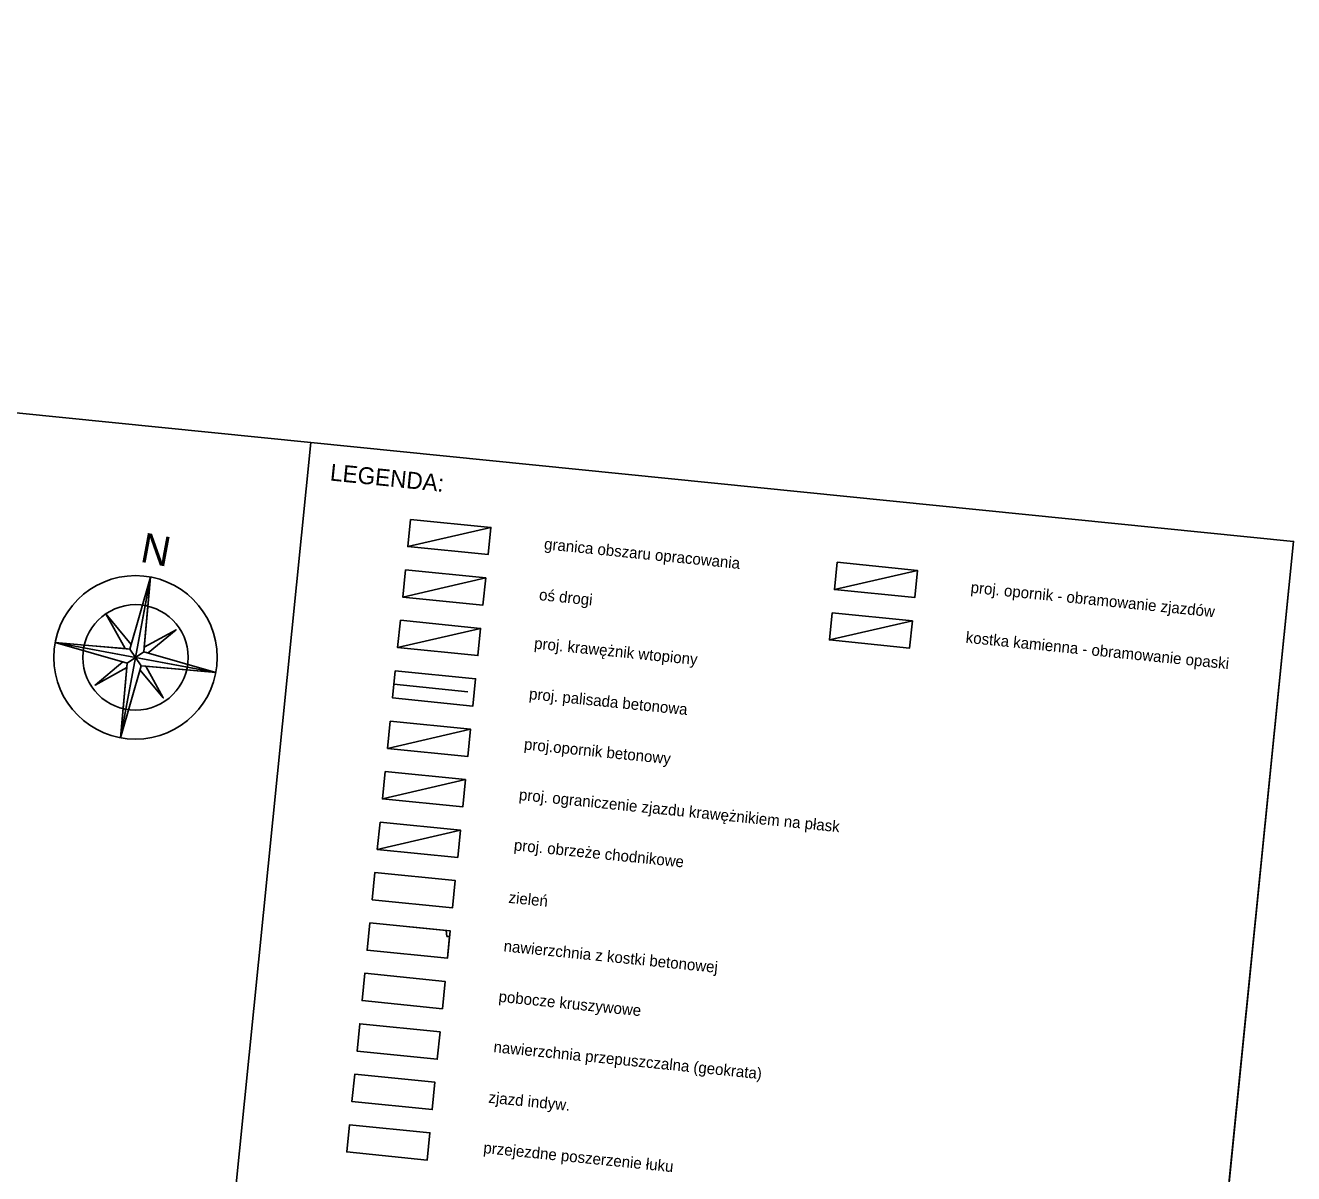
# Model space of a CAD drawing. Extents: x 7481518 to 7481979, y 5775984 to 5776168.
# Drawn here: x 7481859.8 to 7481962.5, y 5776073.9 to 5776166.9 of the extents above; entities that cross this region are included whole.
import ezdxf

# ---------------------------------------------------------------- set-up
doc = ezdxf.new("R2010")
doc.units = 0
for name, color, linetype in [('kraweznik', 7, 'Continuous'), ('numer', 7, 'Continuous'), ('odwierty', 7, 'Continuous'), ('opis', 7, 'Continuous'), ('pomoc', 7, 'Continuous'), ('proj_linia_rozgraniczajaca_kanalizacja', 7, 'Continuous'), ('sciek podchodnikowy', 7, 'Continuous')]:
    doc.layers.add(name, color=color, linetype=linetype)

msp = doc.modelspace()

# ---------------------------------------------------------------- linework, layer by layer
at = {"layer": 'kraweznik'}
for p, q in [((7481893.92, 5776093.06), (7481893.88, 5776093.55)), ((7481894.16, 5776093.08), (7481893.92, 5776093.06))]:
    msp.add_line(p, q, dxfattribs=at)
for points in [[(7481893.88, 5776093.55), (7481887.7, 5776094.17), (7481887.48, 5776091.96), (7481893.98, 5776091.31), (7481894.02, 5776091.65), (7481894.16, 5776093.08)], [(7481887.07, 5776087.88), (7481893.57, 5776087.22), (7481893.79, 5776089.43), (7481887.29, 5776090.09), (7481887.07, 5776087.88)], [(7481886.66, 5776083.79), (7481893.16, 5776083.13), (7481893.38, 5776085.35), (7481886.88, 5776086), (7481886.66, 5776083.79)], [(7481886.24, 5776079.7), (7481892.75, 5776079.05), (7481892.97, 5776081.26), (7481886.47, 5776081.91), (7481886.24, 5776079.7)], [(7481885.83, 5776075.62), (7481892.34, 5776074.96), (7481892.56, 5776077.17), (7481886.06, 5776077.83), (7481885.83, 5776075.62)]]:
    msp.add_lwpolyline(points, dxfattribs=at)
at = {"layer": 'numer'}
for p, q in [((7481889.95, 5776116.48), (7481896.67, 5776118.03)), ((7481888.71, 5776104.22), (7481895.44, 5776105.78))]:
    msp.add_line(p, q, dxfattribs=at)
at = {"layer": 'odwierty'}
msp.add_lwpolyline([(7481887.89, 5776096.05), (7481894.39, 5776095.39), (7481894.62, 5776097.6), (7481888.11, 5776098.26), (7481887.89, 5776096.05)], dxfattribs=at)
at = {"layer": 'opis'}
msp.add_line((7481895.03, 5776101.69), (7481888.3, 5776100.13), dxfattribs=at)
at = {"layer": 'pomoc'}
for p, q in [((7481890.77, 5776124.65), (7481897.5, 5776126.21)), ((7481962.51, 5776125.07), (7481948.28, 5775983.78)), ((7481869.94, 5776122.19), (7481867.51, 5776109.17)), ((7481869.94, 5776122.19), (7481868.26, 5776116.35)), ((7481869.94, 5776122.19), (7481869.4, 5776116.14)), ((7481890.36, 5776120.57), (7481893.72, 5776121.34)), ((7481893.72, 5776121.34), (7481897.09, 5776122.12)), ((7481866.31, 5776119.2), (7481867.89, 5776116.39)), ((7481866.31, 5776119.2), (7481868.36, 5776116.71)), ((7481872, 5776117.92), (7481869.43, 5776116.5)), ((7481872, 5776117.92), (7481869.75, 5776116.04)), ((7481862.22, 5776116.89), (7481875.23, 5776114.46)), ((7481862.22, 5776116.89), (7481868.05, 5776115.21)), ((7481862.22, 5776116.89), (7481868.26, 5776116.35)), ((7481868.26, 5776116.35), (7481868.72, 5776115.68)), ((7481869.4, 5776116.14), (7481868.72, 5776115.68)), ((7481875.23, 5776114.46), (7481869.4, 5776116.14)), ((7481865.45, 5776113.43), (7481867.7, 5776115.32)), ((7481867.51, 5776109.17), (7481868.05, 5776115.21)), ((7481867.51, 5776109.17), (7481869.19, 5776115)), ((7481868.05, 5776115.21), (7481868.72, 5776115.68)), ((7481869.19, 5776115), (7481868.72, 5776115.68)), ((7481875.23, 5776114.46), (7481869.19, 5776115)), ((7481865.45, 5776113.43), (7481868.01, 5776114.85)), ((7481870.97, 5776112.4), (7481869.09, 5776114.65)), ((7481870.97, 5776112.4), (7481869.55, 5776114.97))]:
    msp.add_line(p, q, dxfattribs=at)
for points in [[(7481882.91, 5776133.08), (7481547.45, 5776166.87), (7481533.22, 5776025.59), (7481868.68, 5775991.8)], [(7481868.68, 5775991.8), (7481948.28, 5775983.78), (7481962.51, 5776125.07), (7481882.91, 5776133.08)], [(7481890.99, 5776126.86), (7481897.5, 5776126.21), (7481897.27, 5776124), (7481890.77, 5776124.65)], [(7481925.54, 5776123.38), (7481932.04, 5776122.73), (7481931.82, 5776120.52), (7481925.32, 5776121.17)], [(7481890.58, 5776122.78), (7481897.09, 5776122.12), (7481896.86, 5776119.91), (7481890.36, 5776120.57)], [(7481925.13, 5776119.3), (7481931.63, 5776118.64), (7481931.41, 5776116.43), (7481924.91, 5776117.09)], [(7481890.17, 5776118.69), (7481896.67, 5776118.03), (7481896.45, 5776115.82), (7481889.95, 5776116.48)], [(7481889.76, 5776114.6), (7481896.26, 5776113.95), (7481896.04, 5776111.74), (7481889.54, 5776112.39)], [(7481889.35, 5776110.52), (7481895.85, 5776109.86), (7481895.63, 5776107.65), (7481889.13, 5776108.31)], [(7481888.94, 5776106.43), (7481895.44, 5776105.78), (7481895.22, 5776103.57), (7481888.71, 5776104.22)], [(7481888.53, 5776102.34), (7481895.03, 5776101.69), (7481894.81, 5776099.48), (7481888.3, 5776100.13)], [(7481888.11, 5776098.26), (7481894.62, 5776097.6), (7481894.39, 5776095.39), (7481887.89, 5776096.05)], [(7481887.7, 5776094.17), (7481894.21, 5776093.52), (7481893.98, 5776091.31), (7481887.48, 5776091.96)], [(7481887.29, 5776090.09), (7481893.79, 5776089.43), (7481893.57, 5776087.22), (7481887.07, 5776087.88)], [(7481886.88, 5776086), (7481893.38, 5776085.35), (7481893.16, 5776083.13), (7481886.66, 5776083.79)], [(7481886.47, 5776081.91), (7481892.97, 5776081.26), (7481892.75, 5776079.05), (7481886.24, 5776079.7)], [(7481886.06, 5776077.83), (7481892.56, 5776077.17), (7481892.34, 5776074.96), (7481885.83, 5776075.62)]]:
    msp.add_lwpolyline(points, close=True, dxfattribs=at)
for points in [[(7481869.73, 5776119.82), (7481869.94, 5776122.19), (7481869.51, 5776119.87)], [(7481867.89, 5776116.39), (7481868.26, 5776116.35), (7481868.36, 5776116.71), (7481866.31, 5776119.2), (7481867.89, 5776116.39)], [(7481869.51, 5776119.87), (7481868.72, 5776115.68), (7481869.4, 5776116.14), (7481869.43, 5776116.5), (7481869.73, 5776119.82)], [(7481869.43, 5776116.5), (7481869.4, 5776116.14), (7481869.75, 5776116.04), (7481872, 5776117.92), (7481869.43, 5776116.5)], [(7481864.58, 5776116.68), (7481862.22, 5776116.89), (7481864.53, 5776116.46)], [(7481864.53, 5776116.46), (7481868.72, 5776115.68), (7481868.26, 5776116.35), (7481867.89, 5776116.39), (7481864.58, 5776116.68)], [(7481868.01, 5776114.85), (7481868.05, 5776115.21), (7481867.7, 5776115.32), (7481865.45, 5776113.43), (7481868.01, 5776114.85)], [(7481867.94, 5776111.48), (7481868.72, 5776115.68), (7481868.05, 5776115.21), (7481868.01, 5776114.85), (7481867.72, 5776111.53)], [(7481872.92, 5776114.9), (7481868.72, 5776115.68), (7481869.19, 5776115), (7481869.55, 5776114.97), (7481872.87, 5776114.67)], [(7481869.55, 5776114.97), (7481869.19, 5776115), (7481869.09, 5776114.65), (7481870.97, 5776112.4), (7481869.55, 5776114.97)], [(7481872.87, 5776114.67), (7481875.23, 5776114.46), (7481872.92, 5776114.9)], [(7481867.72, 5776111.53), (7481867.51, 5776109.17), (7481867.94, 5776111.48)]]:
    msp.add_lwpolyline(points, dxfattribs=at)
for radius in [6.62, 4.27]:
    msp.add_circle((7481868.72, 5776115.68), radius, dxfattribs=at)
for start, end in [(76.3862, 79.4296), (76.3862, 79.4296), (166.3862, 169.4296), (166.3862, 169.4296), (346.3862, 349.4296), (346.3862, 349.4296), (256.3862, 259.4296), (256.3862, 259.4296)]:
    msp.add_arc((7481868.72, 5776115.68), 4.27, start, end, dxfattribs=at)
at = {"layer": 'proj_linia_rozgraniczajaca_kanalizacja'}
msp.add_line((7481895.64, 5776112.89), (7481889.65, 5776113.5), dxfattribs=at)
at = {"layer": 'sciek podchodnikowy'}
for p, q in [((7481925.32, 5776121.17), (7481932.04, 5776122.73)), ((7481924.91, 5776117.09), (7481931.63, 5776118.64)), ((7481889.13, 5776108.31), (7481895.85, 5776109.86))]:
    msp.add_line(p, q, dxfattribs=at)

# ---------------------------------------------------------------- texts
at = {"layer": 'pomoc'}
for s, height, rotation, p in [('LEGENDA:', 1.368, 354.2485, (7481884.43, 5776130.01)), ('N', 2.4, 349.4296, (7481869.02, 5776123.44)), ('granica obszaru opracowania', 0.912, 354.2485, (7481901.78, 5776124.44)), ('oś drogi', 0.912, 354.2485, (7481901.37, 5776120.32)), ('proj. opornik - obramowanie zjazdów', 0.912, 354.2485, (7481936.32, 5776120.92)), ('proj. krawężnik wtopiony', 0.912, 354.2485, (7481900.97, 5776116.39)), ('kostka kamienna - obramowanie opaski', 0.912, 354.2485, (7481935.92, 5776116.87)), ('proj. palisada betonowa', 0.912, 354.2485, (7481900.56, 5776112.3)), ('proj.opornik betonowy', 0.912, 354.2485, (7481900.15, 5776108.22)), ('proj. ograniczenie zjazdu krawężnikiem na płask', 0.912, 354.2485, (7481899.74, 5776104.13)), ('proj. obrzeże chodnikowe', 0.912, 354.2485, (7481899.33, 5776100.05)), ('zieleń', 0.912, 354.2485, (7481898.9, 5776095.8)), ('nawierzchnia z kostki betonowej', 0.912, 354.2485, (7481898.5, 5776091.87)), ('pobocze kruszywowe', 0.912, 354.2485, (7481898.09, 5776087.78)), ('nawierzchnia przepuszczalna (geokrata)', 0.912, 354.2485, (7481897.68, 5776083.7)), ('zjazd indyw.', 0.912, 354.2485, (7481897.27, 5776079.61)), ('przejezdne poszerzenie łuku', 0.912, 354.2485, (7481896.86, 5776075.53))]:
    msp.add_text(s, height=height, rotation=rotation, dxfattribs=at).set_placement(p)

doc.saveas('drawing.dxf')
